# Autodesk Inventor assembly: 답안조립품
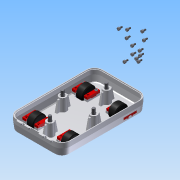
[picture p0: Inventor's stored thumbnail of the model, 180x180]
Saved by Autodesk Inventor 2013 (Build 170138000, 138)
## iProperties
Created: 2015-06
Part Number: 답안조립품
Document SubType Name: Assembly
Designer: Administrator
Author: Administrator
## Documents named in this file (7)
- C:\Documents and Settings\Administrator\바탕 화면\450507V1014\답안조립품.iam
- C:\Documents and Settings\Administrator\바탕 화면\450507V1014\1-본체.ipt
- C:\Documents and Settings\Administrator\바탕 화면\450507V1014\커버.ipt
- C:\Documents and Settings\Administrator\바탕 화면\450507V1014\M4x10.ipt
- C:\Documents and Settings\Administrator\바탕 화면\450507V1014\바퀴.ipt
- C:\Documents and Settings\Administrator\바탕 화면\450507V1014\바퀴고정부.ipt
- C:\Documents and Settings\Administrator\바탕 화면\450507V1014\M2x4.ipt
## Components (20 placed, 3 different names)
1. 1-본체:1
2. M4x10:1
3. M4x10:2
4. M4x10:3
5. M4x10:4
6. M2x4:1
7. M2x4:2
8. M2x4:3
9. M2x4:4
10. M2x4:5
11. M2x4:6
12. M2x4:7
13. M2x4:8
14. M2x4:9
15. M2x4:10
16. M2x4:11
17. M2x4:12
18. M2x4:13
19. M2x4:14
20. M2x4:15
